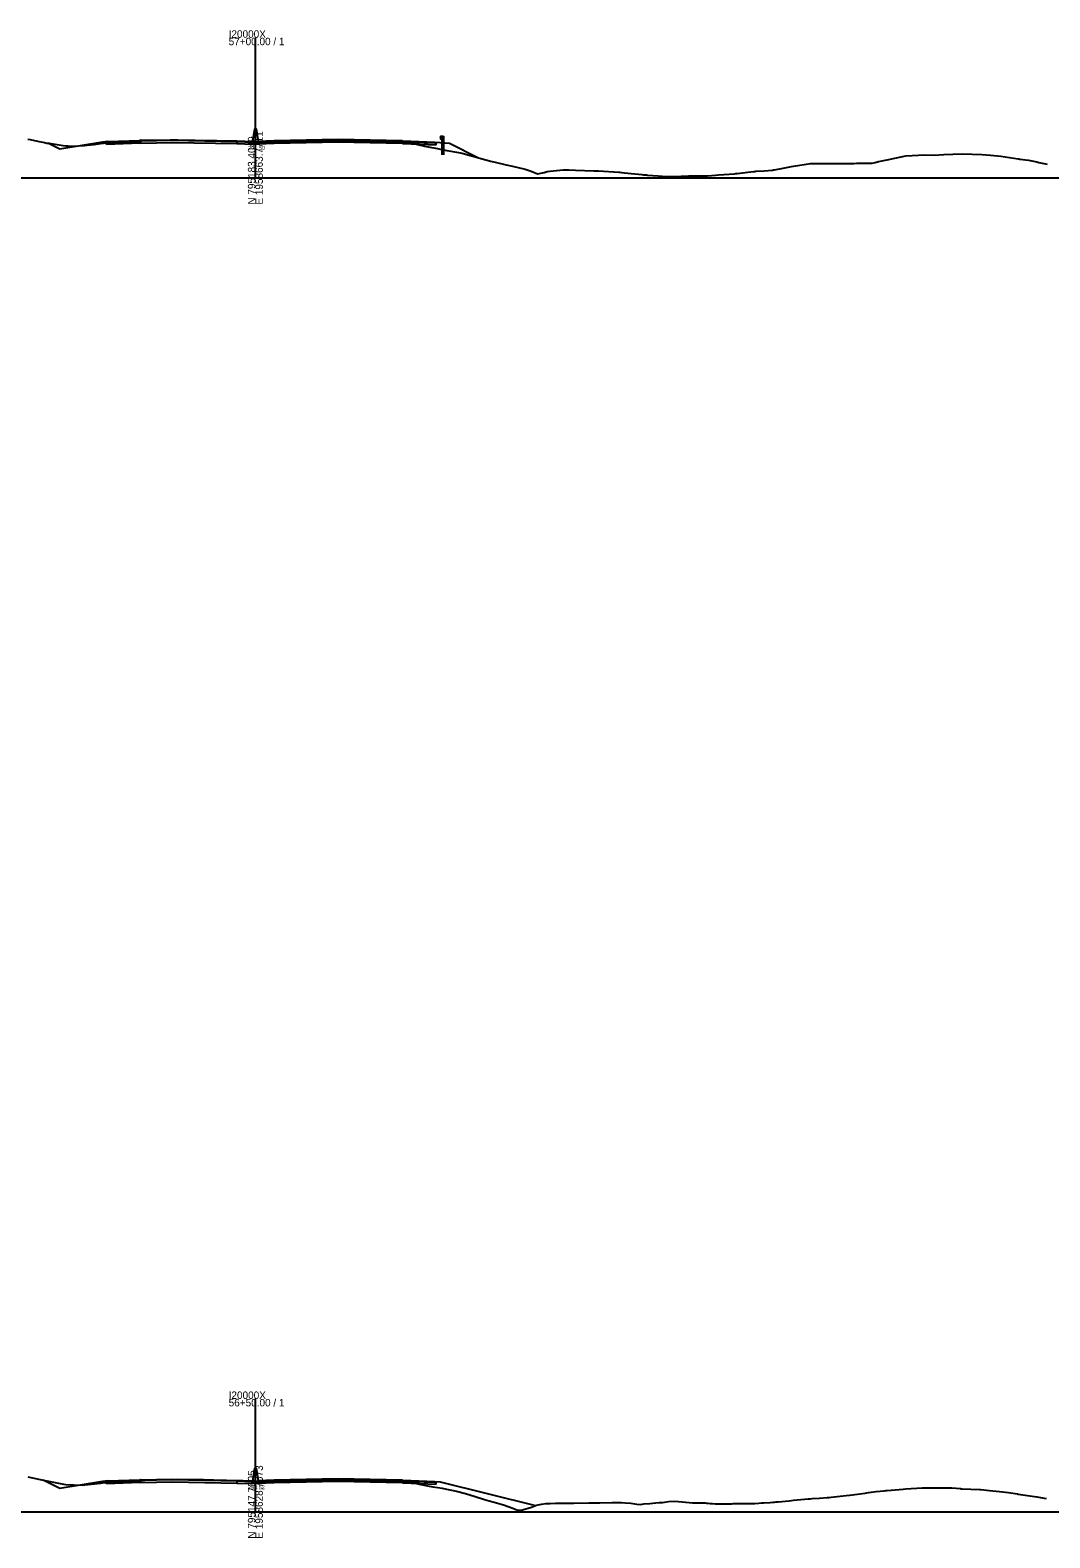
# Model space of a CAD drawing. Extents: x -4026 to 9638, y -10 to 19609.
# Drawn here: x -1734 to -1352, y 6490 to 7055 of the extents above; entities that cross this region are included whole.
import ezdxf

# ---------------------------------------------------------------- set-up
doc = ezdxf.new("R2010")
doc.units = 0
for name, color, linetype in [('RD_GPK_XS_Cell', 7, 'Continuous'), ('RD_XS_Base', 7, 'Continuous'), ('RD_XS_ExGround', 7, 'Continuous'), ('RD_XS_GR', 7, 'Continuous'), ('RD_XS_Greenside', 7, 'Continuous'), ('RD_XS_MedBWall', 7, 'Continuous'), ('RD_XS_Pave', 7, 'Continuous'), ('RD_XS_PaveOvlay', 7, 'Continuous'), ('RD_XS_TieSlope', 7, 'Continuous'), ('RD_XS_TX_Elev_EX', 7, 'Continuous')]:
    doc.layers.add(name, color=color, linetype=linetype)

msp = doc.modelspace()

# ---------------------------------------------------------------- linework, layer by layer
at = {"layer": 'RD_GPK_XS_Cell'}
for p, q in [((-1650, 7000), (-1650, 7052.55)), ((-2000, 7000), (-1650, 7000)), ((-1650, 7000), (-1300, 7000)), ((-1650, 6500), (-1650, 6542.37)), ((-2000, 6500), (-1650, 6500)), ((-1650, 6500), (-1300, 6500))]:
    msp.add_line(p, q, dxfattribs=at)
at = {"layer": 'RD_XS_Base'}
for points in [[(-1705.75, 7013.27), (-1705.25, 7013.29), (-1693.25, 7013.76)], [(-1705.75, 7012.6), (-1705.75, 7013.27)], [(-1693.25, 7013.09), (-1705.75, 7012.6)], [(-1693.25, 7013.76), (-1693, 7013.77)], [(-1693.25, 7013.09), (-1693.25, 7013.76)], [(-1693, 7013.1), (-1693.25, 7013.09)], [(-1657, 7013.53), (-1681, 7014.01), (-1693, 7013.77)], [(-1693, 7013.77), (-1693, 7013.1)], [(-1693, 7013.1), (-1681, 7013.34), (-1657, 7012.86)], [(-1651, 7013.3), (-1657, 7013.53)], [(-1657, 7013.53), (-1657, 7012.86)], [(-1657, 7012.86), (-1651, 7012.63)], [(-1651, 7012.63), (-1651, 7013.3)], [(-1649, 7013.35), (-1643, 7013.6)], [(-1649, 7012.68), (-1649, 7013.35)], [(-1643, 7012.93), (-1649, 7012.68)], [(-1643, 7013.6), (-1619, 7014.08), (-1595, 7013.6)], [(-1643, 7012.93), (-1643, 7013.6)], [(-1595, 7012.93), (-1619, 7013.41), (-1643, 7012.93)], [(-1595, 7013.6), (-1594.75, 7013.59)], [(-1595, 7012.93), (-1595, 7013.6)], [(-1594.75, 7012.92), (-1595, 7012.93)], [(-1594.75, 7013.59), (-1594.75, 7012.92)], [(-1582.25, 7013.09), (-1582.75, 7013.11), (-1594.75, 7013.59)], [(-1594.75, 7012.92), (-1582.25, 7012.42)], [(-1582.25, 7012.42), (-1582.25, 7013.09)], [(-1705.75, 6511.26), (-1705.25, 6511.28), (-1693.25, 6511.76)], [(-1705.75, 6510.59), (-1705.75, 6511.26)], [(-1693.25, 6511.09), (-1705.75, 6510.59)], [(-1693.25, 6511.76), (-1693, 6511.76)], [(-1693.25, 6511.09), (-1693.25, 6511.76)], [(-1693, 6511.09), (-1693.25, 6511.09)], [(-1657, 6511.52), (-1681, 6512.01), (-1693, 6511.76)], [(-1693, 6511.76), (-1693, 6511.09)], [(-1693, 6511.09), (-1681, 6511.34), (-1657, 6510.85)], [(-1651, 6511.29), (-1657, 6511.52)], [(-1657, 6511.52), (-1657, 6510.85)], [(-1657, 6510.85), (-1651, 6510.62)], [(-1651, 6510.62), (-1651, 6511.29)], [(-1649, 6511.38), (-1643, 6511.62)], [(-1649, 6510.71), (-1649, 6511.38)], [(-1643, 6510.95), (-1649, 6510.71)], [(-1643, 6511.62), (-1619, 6512.1), (-1595, 6511.62)], [(-1643, 6510.95), (-1643, 6511.62)], [(-1595, 6510.95), (-1619, 6511.43), (-1643, 6510.95)], [(-1595, 6511.62), (-1594.75, 6511.61)], [(-1595, 6510.95), (-1595, 6511.62)], [(-1594.75, 6510.94), (-1595, 6510.95)], [(-1594.75, 6511.61), (-1594.75, 6510.94)], [(-1582.25, 6511.12), (-1582.75, 6511.14), (-1594.75, 6511.61)], [(-1594.75, 6510.94), (-1582.25, 6510.45)], [(-1582.25, 6510.45), (-1582.25, 6511.12)]]:
    msp.add_lwpolyline(points, dxfattribs=at)
at = {"layer": 'RD_XS_ExGround'}
for points in [[(-1735.19, 7014.57), (-1734.34, 7014.38), (-1731.65, 7013.73), (-1729, 7013.25), (-1728.11, 7013.1), (-1727.21, 7012.99), (-1721.99, 7012.19), (-1721.04, 7012.02), (-1720.08, 7011.98), (-1717.51, 7011.87), (-1714.98, 7012.12), (-1713.97, 7012.21), (-1712.95, 7012.33), (-1710.44, 7012.59), (-1707.96, 7012.89), (-1706.9, 7013.02), (-1704.8, 7013.17), (-1704.03, 7013.22), (-1702.39, 7013.34), (-1699.51, 7013.56), (-1695.82, 7013.76), (-1690.29, 7014.04), (-1681.96, 7014.24), (-1679.05, 7014.3), (-1672.53, 7014.16), (-1667.46, 7014.06), (-1664.42, 7013.99), (-1655.84, 7013.83), (-1651.32, 7013.54), (-1650.8, 7013.51), (-1650.5, 7013.5), (-1650, 7013.5), (-1646.81, 7013.46), (-1642.4, 7013.7), (-1640.86, 7013.77), (-1637.71, 7013.85), (-1629.29, 7014.06), (-1621.43, 7014.18), (-1617.74, 7014.24), (-1608, 7014.01), (-1606.22, 7013.96), (-1599.05, 7013.68), (-1598.43, 7013.66), (-1598.05, 7013.62), (-1594.99, 7013.3), (-1593.66, 7013.16), (-1590.22, 7012.83), (-1588.73, 7012.43), (-1586.69, 7011.94), (-1584.61, 7011.53), (-1583.15, 7011.27), (-1581.72, 7010.98), (-1579.62, 7010.55), (-1577.48, 7010.16), (-1574.7, 7009.66), (-1572.55, 7009.24), (-1570.35, 7008.66), (-1569.01, 7008.31), (-1567.69, 7007.94), (-1565.47, 7007.31), (-1563.22, 7006.67), (-1561.94, 7006.28), (-1560.67, 7005.99), (-1556.09, 7004.91), (-1553.66, 7004.4), (-1548.96, 7003.32), (-1546.65, 7002.53), (-1544.26, 7001.57), (-1541.83, 7002.09), (-1540.72, 7002.46), (-1539.63, 7002.56), (-1534.7, 7003), (-1532.62, 7003.03), (-1530.12, 7002.96), (-1523.18, 7002.73), (-1522.46, 7002.71), (-1521.46, 7002.63), (-1513.84, 7002.22), (-1513.49, 7002.17), (-1512.71, 7002.05), (-1511.68, 7001.88), (-1510.43, 7001.76), (-1509.24, 7001.68), (-1507.88, 7001.55), (-1506.42, 7001.41), (-1505.27, 7001.28), (-1504.55, 7001.21), (-1503.96, 7001.15), (-1503.48, 7001.11), (-1503.08, 7001.01), (-1499.05, 7000.74), (-1498.3, 7000.68), (-1497.55, 7000.64), (-1491.92, 7000.59), (-1490.54, 7000.68), (-1487.69, 7000.78), (-1484.79, 7000.79), (-1484.15, 7000.76), (-1483.52, 7000.76), (-1480.62, 7000.76), (-1477.66, 7001.08), (-1476.51, 7001.2), (-1470.53, 7001.56), (-1470.01, 7001.61), (-1469.5, 7001.67), (-1466.48, 7001.99), (-1463.4, 7002.39), (-1462.94, 7002.46), (-1462.48, 7002.49), (-1459.4, 7002.73), (-1456.27, 7002.94), (-1455.87, 7003), (-1455.47, 7003.06), (-1452.33, 7003.63), (-1449.14, 7004.26), (-1448.46, 7004.4), (-1442.02, 7005.47), (-1441.2, 7005.44), (-1435.94, 7005.46), (-1435.37, 7005.46), (-1434.66, 7005.44), (-1433.76, 7005.44), (-1432.56, 7005.41), (-1430.93, 7005.38), (-1430.51, 7005.36), (-1430.09, 7005.36), (-1429.06, 7005.38), (-1427.71, 7005.42), (-1427.33, 7005.44), (-1426.23, 7005.48), (-1425.63, 7005.46), (-1424.75, 7005.49), (-1423.9, 7005.51), (-1423.26, 7005.53), (-1422.19, 7005.51), (-1421.78, 7005.51), (-1420.3, 7005.5), (-1419.21, 7005.52), (-1418.89, 7005.6), (-1417.8, 7005.85), (-1416.56, 7006.11), (-1415.17, 7006.43), (-1414.12, 7006.63), (-1413.32, 7006.8), (-1412.68, 7006.95), (-1412.16, 7007.07), (-1406.37, 7008.25), (-1399.24, 7008.66), (-1395.76, 7008.58), (-1392.11, 7008.76), (-1388.69, 7008.88), (-1384.98, 7008.99), (-1377.85, 7008.75), (-1374.55, 7008.54), (-1370.72, 7008.11), (-1367.48, 7007.64), (-1364.29, 7007.19), (-1363.94, 7007.17), (-1363.59, 7007.1), (-1360.41, 7006.62), (-1357.28, 7006.02), (-1356.87, 7005.92), (-1356.46, 7005.83), (-1353.33, 7005.11)], [(-1735.26, 6513.19), (-1728.91, 6511.78), (-1728.52, 6511.73), (-1728.13, 6511.65), (-1721.9, 6510.48), (-1721, 6510.32), (-1714.89, 6510.03), (-1713.87, 6510.14), (-1707.87, 6510.82), (-1707.31, 6510.88), (-1705.95, 6510.99), (-1705.34, 6511.04), (-1703.77, 6511.19), (-1699.46, 6511.57), (-1691.41, 6511.96), (-1690.26, 6512.02), (-1688.91, 6512.05), (-1679.11, 6512.31), (-1669.39, 6512.12), (-1667.43, 6512.08), (-1665.67, 6512.05), (-1655.76, 6511.83), (-1654.73, 6511.76), (-1650.78, 6511.53), (-1650, 6511.52), (-1648.81, 6511.51), (-1646.8, 6511.49), (-1643.65, 6511.66), (-1641.09, 6511.8), (-1633.71, 6511.96), (-1629.37, 6512.05), (-1627.22, 6512.09), (-1617.79, 6512.23), (-1613.01, 6512.11), (-1606.15, 6511.95), (-1601.83, 6511.8), (-1598.49, 6511.67), (-1597.18, 6511.54), (-1595.26, 6511.34), (-1590.63, 6510.87), (-1588.64, 6510.48), (-1585.53, 6509.85), (-1583.56, 6509.47), (-1581.63, 6509.15), (-1580.03, 6508.9), (-1578.4, 6508.55), (-1576.49, 6508.16), (-1574.61, 6507.75), (-1571.27, 6506.91), (-1567.6, 6505.79), (-1564.14, 6504.72), (-1562.35, 6504.24), (-1560.59, 6503.71), (-1557.01, 6502.74), (-1553.57, 6501.44), (-1551.74, 6500.68), (-1549.88, 6500.82), (-1546.56, 6501.76), (-1544.67, 6502.51), (-1542.75, 6502.87), (-1541.14, 6503.18), (-1539.54, 6503.21), (-1537.6, 6503.31), (-1534.7, 6503.3), (-1533.68, 6503.29), (-1531.75, 6503.3), (-1531.35, 6503.31), (-1530.63, 6503.32), (-1525.1, 6503.39), (-1521.97, 6503.41), (-1520.98, 6503.43), (-1516.39, 6503.57), (-1514.23, 6503.55), (-1512.85, 6503.57), (-1511.49, 6503.45), (-1509.31, 6503.25), (-1507.1, 6502.93), (-1505.78, 6502.82), (-1504.48, 6503.02), (-1502.24, 6503.2), (-1499.97, 6503.49), (-1498.71, 6503.5), (-1497.46, 6503.61), (-1495.17, 6503.89), (-1492.84, 6504.05), (-1490.09, 6503.83), (-1486.18, 6503.44), (-1485.6, 6503.42), (-1484.93, 6503.41), (-1484.19, 6503.38), (-1481.51, 6503.37), (-1480.98, 6503.33), (-1480.36, 6503.27), (-1479.65, 6503.22), (-1478.78, 6503.16), (-1477.75, 6503.08), (-1477.02, 6503.03), (-1476.52, 6503.04), (-1475.13, 6503.04), (-1473.75, 6503.07), (-1472.76, 6503.08), (-1472.37, 6503.08), (-1471.5, 6503.11), (-1470.99, 6503.12), (-1470.25, 6503.14), (-1469.6, 6503.15), (-1468.99, 6503.18), (-1468.21, 6503.18), (-1467.73, 6503.19), (-1466.82, 6503.18), (-1466.47, 6503.19), (-1465.21, 6503.19), (-1463.95, 6503.18), (-1462.91, 6503.19), (-1461.4, 6503.3), (-1460.35, 6503.37), (-1459.47, 6503.4), (-1457.1, 6503.6), (-1456.2, 6503.67), (-1455.5, 6503.74), (-1454.94, 6503.78), (-1454.48, 6503.81), (-1454.09, 6503.84), (-1450.06, 6504.21), (-1449.21, 6504.28), (-1448.37, 6504.37), (-1442.93, 6504.89), (-1442.14, 6504.96), (-1441.35, 6505.02), (-1438.6, 6505.21), (-1435.8, 6505.42), (-1435.07, 6505.47), (-1434.34, 6505.55), (-1428.67, 6506.13), (-1427.32, 6506.31), (-1424.46, 6506.69), (-1421.54, 6507.09), (-1420.92, 6507.18), (-1420.31, 6507.26), (-1417.39, 6507.66), (-1414.41, 6507.97), (-1413.85, 6508.03), (-1413.3, 6508.08), (-1410.32, 6508.34), (-1407.28, 6508.57), (-1406.28, 6508.64), (-1400.16, 6509.03), (-1399.71, 6509.05), (-1399.27, 6509.06), (-1396.17, 6509.09), (-1393.03, 6509.08), (-1392.64, 6509.08), (-1392.26, 6509.07), (-1389.1, 6508.99), (-1385.9, 6508.75), (-1385.57, 6508.71), (-1385.24, 6508.71), (-1378.77, 6508.43), (-1378.23, 6508.39), (-1374.96, 6508), (-1371.22, 6507.65), (-1367.89, 6507.27), (-1364.51, 6506.76), (-1364.2, 6506.72), (-1357.19, 6505.7), (-1353.75, 6505.07)]]:
    msp.add_lwpolyline(points, dxfattribs=at)
at = {"layer": 'RD_XS_GR'}
for points in [[(-1580.51, 7015.68), (-1580.75, 7015.38)], [(-1580.75, 7015.38), (-1580.52, 7015.08)], [(-1580.52, 7015.08), (-1580.75, 7014.8)], [(-1580.75, 7014.8), (-1580.51, 7014.5)], [(-1580.51, 7014.5), (-1580.51, 7015.68)], [(-1580.51, 7015.68), (-1580.02, 7015.68)], [(-1580.02, 7014.5), (-1580.51, 7014.5)], [(-1580.02, 7015.68), (-1579.52, 7015.68)], [(-1580.02, 7013.22), (-1580.02, 7015.68)], [(-1580.02, 7015.68), (-1580.02, 7014.5)], [(-1580.02, 7008.72), (-1580.02, 7013.22)], [(-1580.02, 7013.22), (-1579.52, 7013.18)], [(-1579.52, 7013.18), (-1580.02, 7013.22)], [(-1579.52, 7015.68), (-1579.52, 7013.18)], [(-1579.52, 7013.18), (-1579.52, 7008.72)]]:
    msp.add_lwpolyline(points, dxfattribs=at)
at = {"layer": 'RD_XS_Greenside'}
for points in [[(-1707.25, 7013.46), (-1723.25, 7010.79)], [(-1705.25, 7013.62), (-1707.25, 7013.46)], [(-1582.75, 7013.45), (-1580.75, 7013.28)], [(-1580.75, 7013.28), (-1577.25, 7012.99), (-1566.45, 7007.59)], [(-1707.25, 6511.46), (-1723.25, 6508.79)], [(-1705.25, 6511.62), (-1707.25, 6511.46)], [(-1582.75, 6511.47), (-1580.75, 6511.3)], [(-1580.75, 6511.3), (-1545.02, 6502.37)]]:
    msp.add_lwpolyline(points, dxfattribs=at)
at = {"layer": 'RD_XS_MedBWall'}
for points in [[(-1651, 7013.63), (-1650.25, 7018.35), (-1649.75, 7018.35), (-1649, 7013.68)], [(-1651, 7012.63), (-1651, 7013.63)], [(-1649, 7013.68), (-1649, 7012.63)], [(-1649, 7012.63), (-1651, 7012.63)], [(-1651, 6511.62), (-1650.25, 6516.38), (-1649.75, 6516.38), (-1649, 6511.71)], [(-1651, 6510.62), (-1651, 6511.62)], [(-1649, 6510.62), (-1651, 6510.62)], [(-1649, 6511.71), (-1649, 6510.62)]]:
    msp.add_lwpolyline(points, dxfattribs=at)
at = {"layer": 'RD_XS_Pave'}
for points in [[(-1705.25, 7013.45), (-1693.25, 7013.93)], [(-1693.25, 7013.76), (-1705.25, 7013.29)], [(-1705.25, 7013.29), (-1705.25, 7013.45)], [(-1693.25, 7013.93), (-1693, 7013.94)], [(-1693.25, 7013.76), (-1693.25, 7013.93)], [(-1693, 7013.77), (-1693.25, 7013.76)], [(-1693, 7013.94), (-1681, 7014.18), (-1657, 7013.7)], [(-1657, 7013.53), (-1681, 7014.01), (-1693, 7013.77)], [(-1693, 7013.94), (-1693, 7013.77)], [(-1657, 7013.7), (-1657, 7013.53)], [(-1657, 7013.7), (-1651, 7013.47)], [(-1651, 7013.3), (-1657, 7013.53)], [(-1651, 7013.47), (-1651, 7013.3)], [(-1643, 7013.77), (-1649, 7013.52)], [(-1649, 7013.35), (-1643, 7013.6)], [(-1649, 7013.52), (-1649, 7013.35)], [(-1595, 7013.77), (-1619, 7014.25), (-1643, 7013.77)], [(-1643, 7013.6), (-1619, 7014.08), (-1595, 7013.6)], [(-1643, 7013.77), (-1643, 7013.6)], [(-1595, 7013.77), (-1594.75, 7013.76)], [(-1595, 7013.6), (-1595, 7013.77)], [(-1594.75, 7013.59), (-1595, 7013.6)], [(-1594.75, 7013.76), (-1594.75, 7013.59)], [(-1582.75, 7013.28), (-1594.75, 7013.76)], [(-1594.75, 7013.59), (-1582.75, 7013.11)], [(-1582.75, 7013.11), (-1582.75, 7013.28)], [(-1705.25, 6511.45), (-1693.25, 6511.93)], [(-1693.25, 6511.76), (-1705.25, 6511.28)], [(-1705.25, 6511.28), (-1705.25, 6511.45)], [(-1693.25, 6511.93), (-1693, 6511.93)], [(-1693.25, 6511.76), (-1693.25, 6511.93)], [(-1693, 6511.76), (-1693.25, 6511.76)], [(-1693, 6511.93), (-1681, 6512.17), (-1657, 6511.69)], [(-1657, 6511.52), (-1681, 6512.01), (-1693, 6511.76)], [(-1693, 6511.93), (-1693, 6511.76)], [(-1657, 6511.69), (-1657, 6511.52)], [(-1657, 6511.69), (-1651, 6511.46)], [(-1651, 6511.29), (-1657, 6511.52)], [(-1651, 6511.46), (-1651, 6511.29)], [(-1643, 6511.79), (-1649, 6511.55)], [(-1649, 6511.38), (-1643, 6511.62)], [(-1649, 6511.55), (-1649, 6511.38)], [(-1595, 6511.79), (-1619, 6512.27), (-1643, 6511.79)], [(-1643, 6511.62), (-1619, 6512.1), (-1595, 6511.62)], [(-1643, 6511.79), (-1643, 6511.62)], [(-1595, 6511.79), (-1594.75, 6511.78)], [(-1595, 6511.62), (-1595, 6511.79)], [(-1594.75, 6511.61), (-1595, 6511.62)], [(-1594.75, 6511.78), (-1594.75, 6511.61)], [(-1582.75, 6511.3), (-1594.75, 6511.78)], [(-1594.75, 6511.61), (-1582.75, 6511.14)], [(-1582.75, 6511.14), (-1582.75, 6511.3)]]:
    msp.add_lwpolyline(points, dxfattribs=at)
at = {"layer": 'RD_XS_PaveOvlay'}
for points in [[(-1705.25, 7013.62), (-1693.25, 7014.1)], [(-1693.25, 7013.93), (-1705.25, 7013.45)], [(-1705.25, 7013.45), (-1705.25, 7013.62)], [(-1693, 7014.11), (-1693.25, 7014.1)], [(-1693.25, 7014.1), (-1693.25, 7013.93)], [(-1693.25, 7013.93), (-1693, 7013.94)], [(-1693, 7014.11), (-1681, 7014.35), (-1657, 7013.87)], [(-1657, 7013.7), (-1681, 7014.18), (-1693, 7013.94)], [(-1693, 7013.94), (-1693, 7014.11)], [(-1657, 7013.87), (-1657, 7013.7)], [(-1657, 7013.87), (-1651, 7013.63)], [(-1651, 7013.47), (-1657, 7013.7)], [(-1651, 7013.63), (-1651, 7013.47)], [(-1643, 7013.93), (-1649, 7013.68)], [(-1649, 7013.52), (-1643, 7013.77)], [(-1649, 7013.68), (-1649, 7013.52)], [(-1595, 7013.93), (-1619, 7014.41), (-1643, 7013.93)], [(-1643, 7013.77), (-1619, 7014.25), (-1595, 7013.77)], [(-1643, 7013.93), (-1643, 7013.77)], [(-1595, 7013.77), (-1595, 7013.93)], [(-1595, 7013.93), (-1594.75, 7013.93)], [(-1594.75, 7013.76), (-1595, 7013.77)], [(-1594.75, 7013.93), (-1594.75, 7013.76)], [(-1594.75, 7013.93), (-1582.75, 7013.45)], [(-1582.75, 7013.28), (-1594.75, 7013.76)], [(-1582.75, 7013.45), (-1582.75, 7013.28)], [(-1705.25, 6511.62), (-1693.25, 6512.1)], [(-1693.25, 6511.93), (-1705.25, 6511.45)], [(-1705.25, 6511.45), (-1705.25, 6511.62)], [(-1693.25, 6512.1), (-1693.25, 6511.93)], [(-1693, 6512.1), (-1693.25, 6512.1)], [(-1693.25, 6511.93), (-1693, 6511.93)], [(-1693, 6512.1), (-1681, 6512.34), (-1657, 6511.86)], [(-1657, 6511.69), (-1681, 6512.17), (-1693, 6511.93)], [(-1693, 6511.93), (-1693, 6512.1)], [(-1657, 6511.86), (-1657, 6511.69)], [(-1657, 6511.86), (-1651, 6511.62)], [(-1651, 6511.46), (-1657, 6511.69)], [(-1651, 6511.62), (-1651, 6511.46)], [(-1643, 6511.96), (-1649, 6511.71)], [(-1649, 6511.55), (-1643, 6511.79)], [(-1649, 6511.71), (-1649, 6511.55)], [(-1595, 6511.96), (-1619, 6512.44), (-1643, 6511.96)], [(-1643, 6511.79), (-1619, 6512.27), (-1595, 6511.79)], [(-1643, 6511.96), (-1643, 6511.79)], [(-1595, 6511.79), (-1595, 6511.96)], [(-1595, 6511.96), (-1594.75, 6511.95)], [(-1594.75, 6511.78), (-1595, 6511.79)], [(-1594.75, 6511.95), (-1594.75, 6511.78)], [(-1594.75, 6511.95), (-1582.75, 6511.47)], [(-1582.75, 6511.3), (-1594.75, 6511.78)], [(-1582.75, 6511.47), (-1582.75, 6511.3)]]:
    msp.add_lwpolyline(points, dxfattribs=at)
at = {"layer": 'RD_XS_TieSlope'}
for points in [[(-1723.25, 7010.79), (-1727.78, 7013.06)], [(-1723.25, 6508.79), (-1729.48, 6511.9)]]:
    msp.add_lwpolyline(points, dxfattribs=at)

# ---------------------------------------------------------------- texts
at = {"layer": 'RD_GPK_XS_Cell'}
for s, p in [('57+00.00 / 1', (-1660, 7049.75)), ('I20000X', (-1660, 7052.55)), ('I20000X', (-1660, 6542.37)), ('56+50.00 / 1', (-1660, 6539.57))]:
    msp.add_text(s, height=2.8, dxfattribs=at).set_placement(p)
for s, p in [('N 795183.4049', (-1650, 6990)), ('E 1958663.7711', (-1647.2, 6990)), ('E 1958628.7073', (-1647.2, 6490)), ('N 795147.7605', (-1650, 6490))]:
    msp.add_text(s, height=2.8, rotation=90, dxfattribs=at).set_placement(p)
at = {"layer": 'RD_XS_TX_Elev_EX'}
for s, p in [('291.50', (-1652.69, 7010.5)), ('293.52', (-1652.8, 6508.52))]:
    msp.add_text(s, height=1.5, dxfattribs=at).set_placement(p)

doc.saveas('drawing.dxf')
